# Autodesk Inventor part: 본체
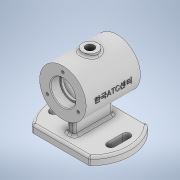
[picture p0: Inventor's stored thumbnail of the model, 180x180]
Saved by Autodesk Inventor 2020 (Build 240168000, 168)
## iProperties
Created: 2021-09
Part Number: 본체
Material: 일반
Document SubType Name: Modeling
Designer: Administrator
Density: 1 g/cm^3
Appearance: 기본값
Mass: 173.238 g
Surface Area: 487.435 cm^2
Volume: 173.238 cm^3
Author: Administrator
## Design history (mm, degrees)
sketch "스케치1"
  geometry: L1 (52.5, 0)-(-52.5, 0); L2 (36.742, -37.5)-(-36.742, -37.5); L3 (36.742, 37.5)-(-36.742, 37.5); A1 r 52.5 centre (0, 0) between (52.5, 0) and (-52.5, 0); 2 further points
  constraints: 6 end point, 6 point on circle, 2 coincident, 2 parallel, 1 centre point, 1 horizontal, 1 midpoint
  dimensions: "d0" = 105 diameter of A1; "d1" = 37.5 distance between parallel lines of L1 L2; "d2" = 37.5 distance between parallel lines of L1 L3
extrude "돌출1" new body sketch "스케치1" distance "d3" = 10; taper "d4" = 0 deg
sketch "스케치2"
  geometry: L1 (-37, -10)-(-37, 10); L2 (-32, -10)-(-32, 10); L3 (-42, 10)-(-42, -10); L4 (-36.742, -37.5)-(36.742, -37.5) reference; L5 (0, -37.5)-(0, 37.5); L6 (36.742, 37.5)-(-36.742, 37.5) reference; L7 (32, -10)-(32, 10); L8 (42, 10)-(42, -10); A1 r 5 centre (-37, -10) between (-42, -10) and (-32, -10); A2 r 5 centre (-37, 10) between (-32, 10) and (-42, 10); A3 r 5 centre (37, 10) between (42, 10) and (32, 10); A4 r 5 centre (37, -10) between (32, -10) and (42, -10); 2 further points
  constraints: 14 end point, 8 point on circle, 6 symmetric about line, 4 centre point, 4 tangent, 3 midpoint, 1 horizontal alignment, 1 parallel, 1 vertical, 2 other
  dimensions: "d5" = 20 distance of L1.end L1.start; "d6" = 37 distance of point (-37, 0) point (0, 0); "d7" = 10 distance from line of L2.end L3
extrude "돌출2" cut sketch "스케치2" extent not by distance; stored distance "d8" = 0; taper "d9" = 0 deg
sketch "스케치3"
  geometry: C1 r 30 at (0, 62); 1 further point
  constraints: 1 centre point, 1 vertical alignment
  dimensions: "d10" = 60 diameter of C1; "d11" = 62 distance of point (0, 0) C1.centre
extrude "돌출3" join sketch "스케치3" stored distance "d12" = 70; taper "d13" = 0 deg
sketch "스케치4"
  geometry: L1 (62, 25)-(0, 25); L2 (0, 25)-(0, -25); L3 (0, -25)-(62, -25); L4 (62, -25)-(62, 25); L5 (0, 10)-(0, -10) reference; L6 (0, -37.5)-(10, -37.5) reference; 1 further point
  constraints: 8 end point, 2 parallel, 1 collinear, 1 horizontal, 1 perpendicular
  dimensions: "d14" = 50 distance between parallel lines of L3 L1; "d15" = 12.5 distance between parallel lines of L6 L3; "d16" = 62 distance between parallel lines of L2 L4
extrude "돌출4" join sketch "스케치4" stored distance "d17" = 10; taper "d18" = 0 deg
node "작업 평면2"
  node "작업 평면1"
sketch "스케치5"
  geometry: C1 r 10 at (0, 0); 1 further point
  constraints: 1 centre point, 1 coincident
  dimensions: "d20" = 20 diameter of C1
extrude "돌출5" join sketch "스케치5" distance "d21" = 33; taper "d22" = 0 deg
sketch "스케치6"
  geometry: L1 (92, 35)-(32, 35) reference; L2 (62, 35)-(62, -35); L3 (32, -35)-(92, -35) reference; L4 (62, 35)-(78, 35); L5 (78, 35)-(78, 23); L6 (78, 23)-(76, 23); L7 (76, 23)-(76, 20); L8 (76, 20)-(87, 20); L9 (87, 20)-(87, -20); L10 (87, -20)-(76, -20); L11 (76, -20)-(76, -23); L12 (76, -23)-(78, -23); L13 (78, -23)-(78, -35); L14 (78, -35)-(62, -35); 1 further point
  constraints: 24 end point, 8 perpendicular, 2 midpoint, 2 point on line, 1 collinear, 1 vertical
  dimensions: "d23" = 28 diameter of L7 L2; "d24" = 32 diameter of L5 L2; "d25" = 50 diameter of L9 L2; "d26" = 28 diameter of L11 L2; "d27" = 32 diameter of L13 L2; "d28" = 12 distance from line of L14 L12.end; "d29" = 3 distance from line of L10 L12.end; "d30" = 3 distance from line of L5.end L8; "d31" = 40 distance between parallel lines of L10 L8
revolve "회전1" sketch "스케치6" stored, may be unused: angle "d32" = 90 deg
sketch "스케치7"
  geometry: C1 r 10 at (0, 0) reference; 2 further points
  constraints: 1 coincident
hole "구멍1" sketch "스케치7" at (0, 0) diameter "d33" = 10.917; stored, may be unused: countersink angle "d37" = 90 deg, drill point angle "d39" = 118 deg; dims "d34" = 20, "d35" = 4, "d36" = 2, "d38" = 21
sketch "스케치8" dims "d40" = 46
  geometry: C1 r 30 at (0, 0) reference; 3 further points
  constraints: 2 vertical alignment, 1 coincident, 2 other
hole "구멍2" sketch "스케치8" at (0, 23) diameter "d41" = 3.45873; stored, may be unused: countersink angle "d45" = 90 deg, drill point angle "d47" = 118 deg; dims "d42" = 8, "d43" = 4, "d44" = 2, "d46" = 10
fillet "모깎기1" dims "d51" = 0.3
chamfer "모따기3" distance "d58" = 1; stored, may be unused: second distance "d59" = 2, angle "d60" = 45 deg
chamfer "모따기4" distance "d61" = 1; stored, may be unused: second distance "d62" = 2, angle "d63" = 45 deg
fillet "모깎기2" dims "d64" = 3
node "작업 평면4"
  node "작업 평면3"
sketch "스케치9"
  geometry: L1 (30, -35)-(30, 35) reference; L2 (30, 35)-(-30, 35) reference; 2 further points
  constraints: 1 other
  dimensions: "d66" = 35 distance from line of point (0, 0) L2; "d67" = 30 distance from line of L1 point (0, 0)
feature "엠보싱1" sketch "스케치9" dims "d5" = 20, "d6" = 37, "d7" = 10, "d68" = 0.5, "d69" = 0
node "솔리드1"
pattern_circular "원형 패턴1" dims angle "d49" = 360 deg
mirror "미러1"
feature "A9D066F2-1C7D-4E18-AEED-F7BC21143FA4" dims "d33" = 10.917, "d34" = 20, "d35" = 4, "d36" = 2, "d37" = 90 deg, "d38" = 21, "d39" = 118 deg
other parameters: "d19" = 3
